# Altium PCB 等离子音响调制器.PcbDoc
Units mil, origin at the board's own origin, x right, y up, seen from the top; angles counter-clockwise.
Board outline 3937.01 x 2362.2 mil, 2 copper layers (Top Layer, Bottom Layer); 73 components, 35 nets, 187 pads, 240 vias.
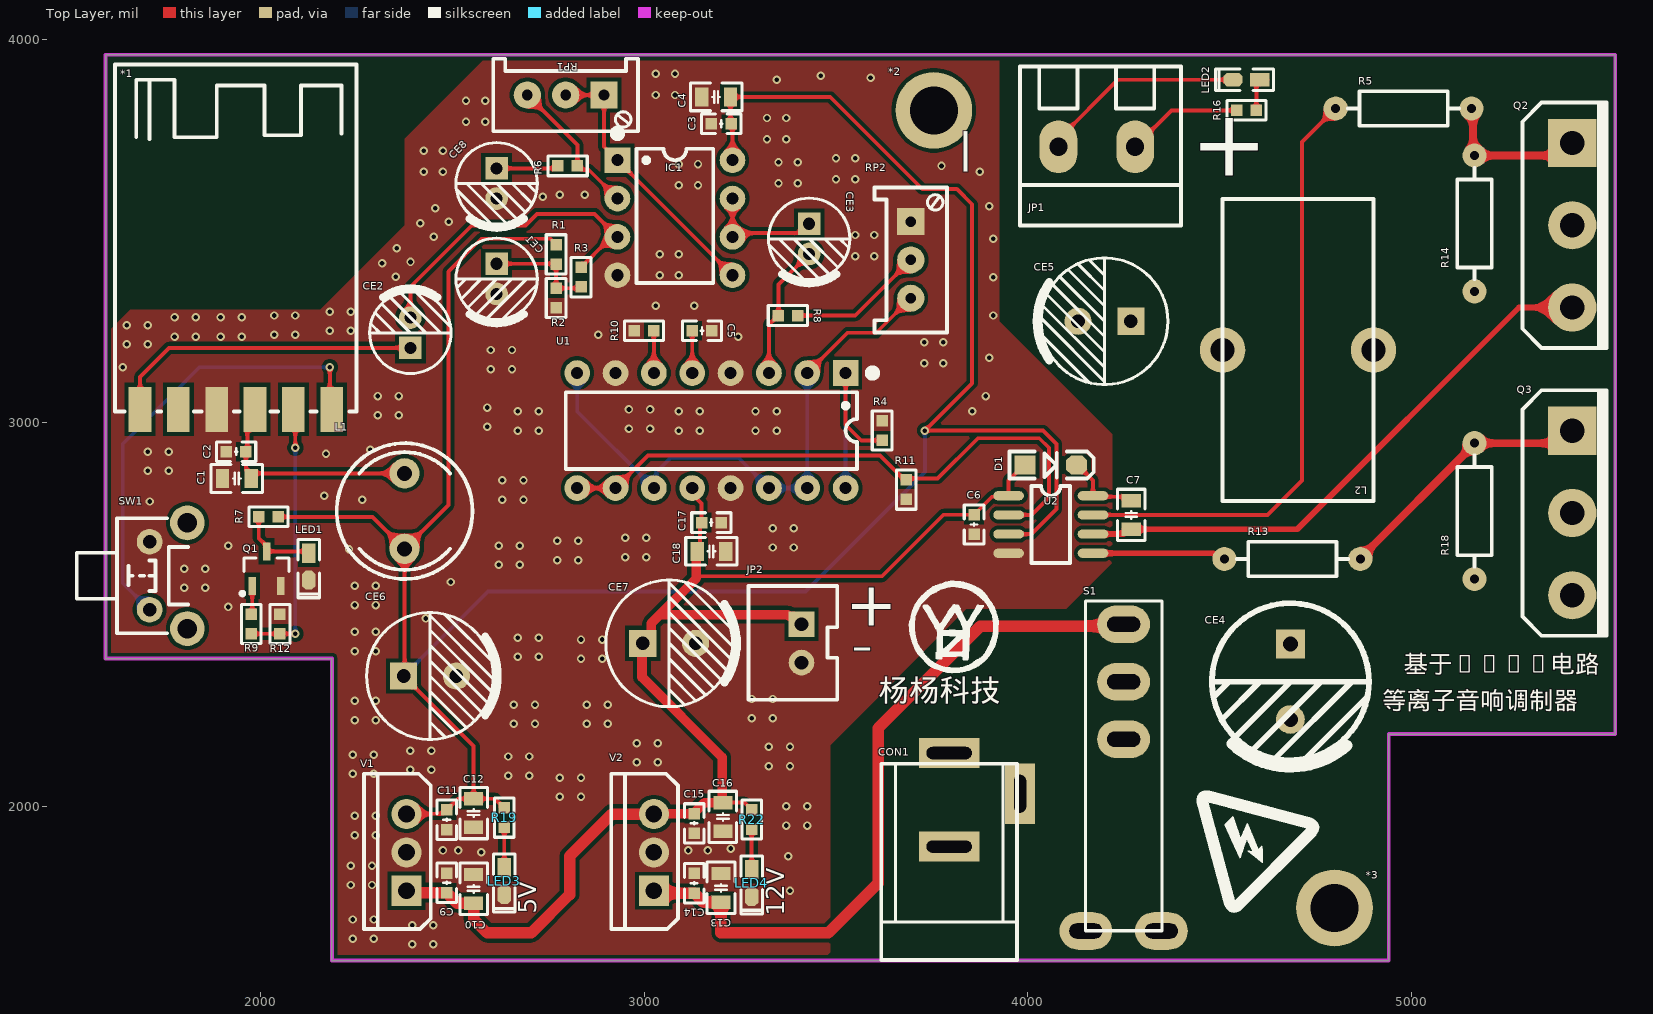
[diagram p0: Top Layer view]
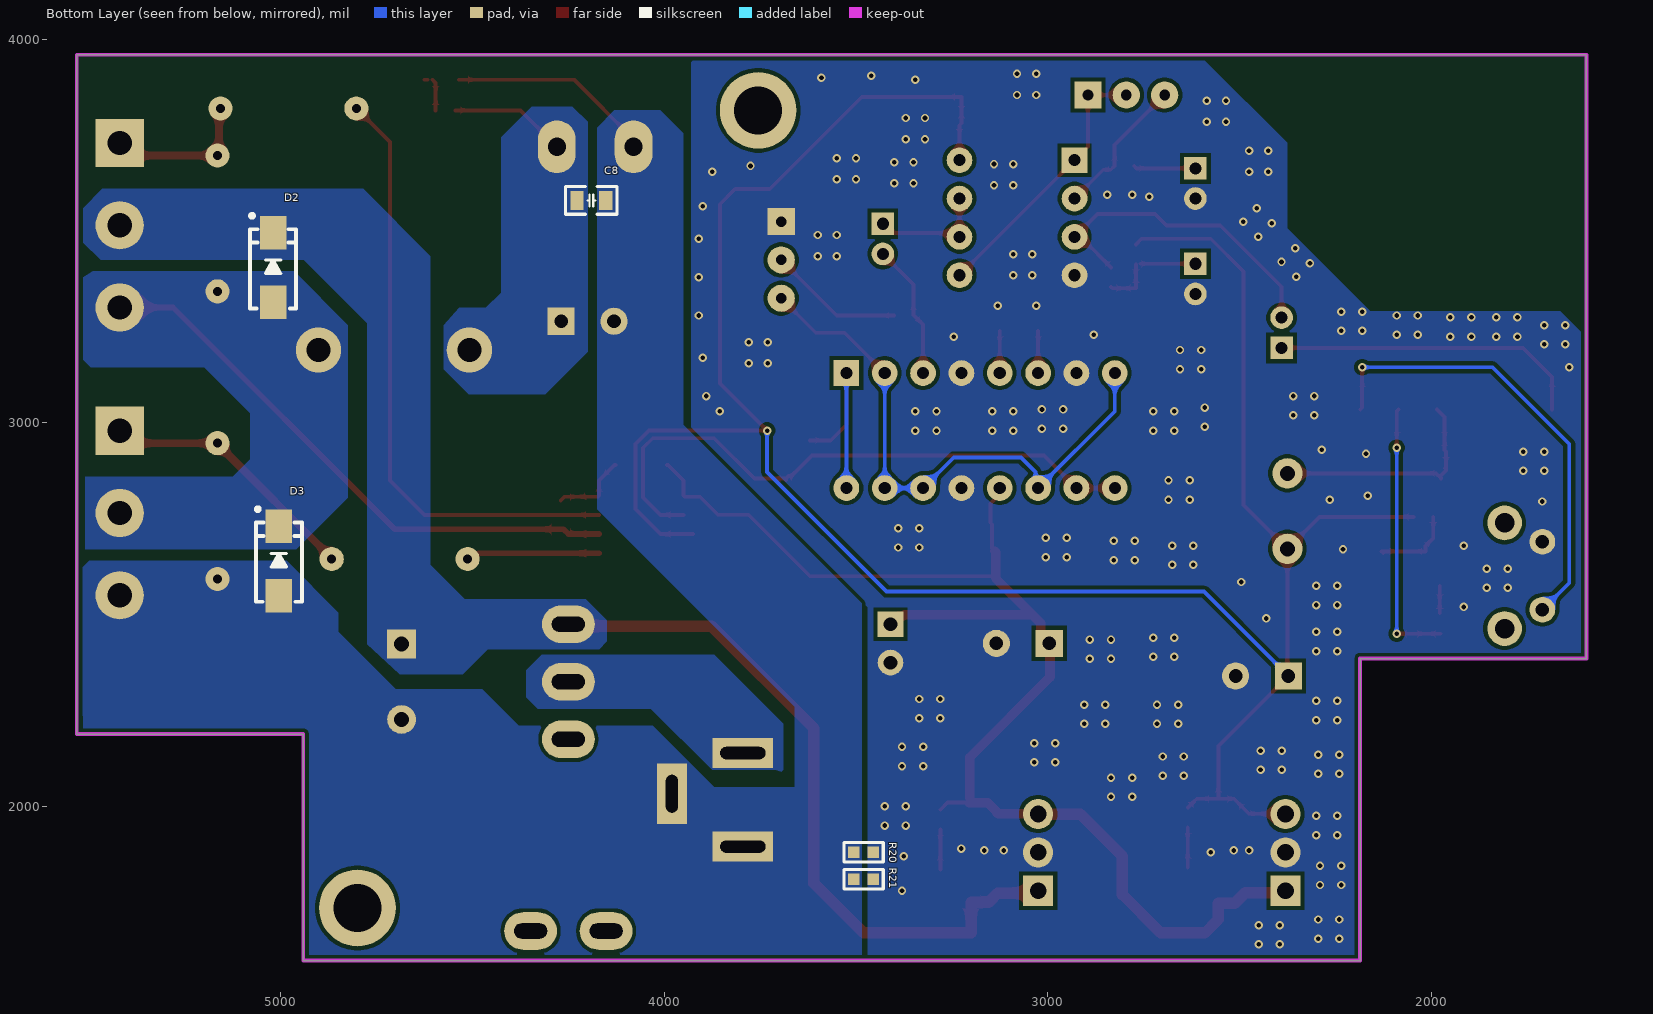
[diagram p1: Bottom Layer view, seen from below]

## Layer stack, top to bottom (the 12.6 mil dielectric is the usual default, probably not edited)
Top Solder: solder mask 0.4, Solder Resist, Dk 3.5
Top Layer: signal copper 1.4
Dielectric 1: dielectric 12.6, FR-4, Dk 4.8
Bottom Layer: signal copper 1.4
Bottom Solder: solder mask 0.4, Solder Resist, Dk 3.5

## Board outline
1595,2385.2 2185.55,2385.2 2185.55,1597.8 4941.46,1597.8 4941.46,2188.35 5532.01,2188.35 5532.01,3960 1595,3960

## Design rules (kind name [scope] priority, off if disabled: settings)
Clearance [All] p1: gap=10 ignorepadtopadclearanceinfootprint=FALSE except(0: Arc-Hole Track-Hole SMDPad-Hole THPad-Hole Via-Hole Fill-Hole Poly-Hole Region-Hole Text-Hole)
PlaneConnect [All] p1: planeconnectstyle=Direct reliefexpansion=20 reliefentries=4 reliefconductorwidth=10 reliefairgap=10
PolygonConnect [All] p1: connectstyle=Direct reliefconductorwidth=10 reliefentries=4 polygonreliefangle="90 Angle" airgapwidth=10
RoutingVias [All] p1: holewidth=28 width=50 viastyle="Through Hole" minholewidth=28 minwidth=50 maxholewidth=28 maxwidth=50
SolderMaskExpansion [All] p1: expansion=4 istentingtop=FALSE
Width [All] p1: maxlimit=10 minlimit=10 preferedwidth=10
29 further rules are at their usual default settings.

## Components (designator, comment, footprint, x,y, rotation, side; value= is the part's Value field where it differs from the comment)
*1 "MH-M18蓝牙音频模块" MH-M18蓝牙音频模块 1620,3935 r270 top
*2 "M3" "M3 125X200" 3755,3815 r0 top
*3 "M3" "M3 125X200" 4800,1735 r0 top
C1 "105" "C 0805_L" 1937.4,2855 r0 top
C2 "104" "C 0603_L" 1935.59,2925 r0 top
C3 "104" "C 0603_L" 3200.59,3780 r0 top
C4 "105" "C 0805_L" 3187.4,3850 r0 top
C5 "1nF" "C 0603_L" 3150.59,3240 r0 top
C6 "104" "C 0603_L" 3860,2735 r90 top
C7 "105\1uF" "C 0805_L" 4270,2760 r90 top
C8 "104" "C 0805_L" 4190,3580 r180 bottom
C9 "104" "C 0603_L" 2485,1800.59 r270 top
C10 "105" "C 0805_L" 2555,1785 r270 top
C11 "104" "C 0603_L" 2485,1965 r90 top
C12 "105" "C 0805_L" 2555,1982.4 r90 top
C13 "105" "C 0805_L" 3200,1787.6 r270 top
C14 "104" "C 0603_L" 3130,1799.41 r270 top
C15 "104" "C 0603_L" 3130,1955.59 r90 top
C16 "105" "C 0805_L" 3205,1972.4 r90 top
C17 "104" "C 0603_L" 3175,2740 r180 top
C18 "105" "C 0805_L" 3175,2665 r180 top
CE1 "22uF/16V" "CAP 2.0*5*11" 2615,3375.63 r270 top
CE2 "22uF/16V" "CAP 2.0*5*11" 2390,3235 r90 top
CE3 "10uF/16V" "CAP 2.0*5*11" 3430,3480 r270 top
CE4 "47uF/35V" "CAP 5.0*10*12.5" 4685,2325 r270 top
CE5 "47uF/35V" "CAP 3.5*8*11.5" 4200,3265 r180 top
CE6 "10uF/16V" "CAP 3.5*8*11.5 - GD" 2441.1,2340 r0 top
CE7 "10uF/16V" "CAP 3.5*8*11.5 - GD" 3065,2425 r0 top
CE8 "22uF/16V" "CAP 2.0*5*11" 2615,3624.37 r270 top
CON1 "3.5*1.3" DC-005 3795,1895 r270 top
D1 "FR107" SOD-123 4060,2890 r0 top
D2 "SS210" SMA 5020,3405 r90 bottom
D3 "SS210" SMA 5005,2640 r90 bottom
IC1 "NE5532" DIP8-300 3080,3535 r0 top
JP1 "HDR-1X2" KF128-5.08-2P 4180,3720 r180 top
JP2 "HDR-1X2" XH2.54-LI-2P 3410,2425 r270 top
L1 "10uH" PK0810 2375,2770 r270 top
L2 "33uH" 65125 4705,3190 r180 top
LED1 "蓝色" "LED 0603Y" 2125,2625 r270 top
LED2 "红色" "LED 0603Y" 4570,3895 r180 top
LED3 "红色" "LED 0603Y" 2635,1805 r270 top
LED4 "红色" "LED 0603Y" 3280,1800 r270 top
Q1 "SS8050" SOT23-3N 2015,2620 r0 top
Q2 "IRFP250" TO247A 5420,3515.43 r270 top
Q3 "IRFP250" TO247A 5420,2765 r270 top
R1 "22K" "R 0603_L" 2770,3439.41 r90 top
R2 "22K" "R 0603_L" 2770,3325.59 r90 top
R3 "22K" "R 0603_L" 2835,3380 r270 top
R4 "1K" "R 0603_L" 3620,2980 r270 top
R5 "10" "RS 1/4W" 4980,3820 r180 top
R6 "5K" "R 0603_L" 2800,3670 r180 top
R7 "1K" "R 0603_L" 2020,2755 r180 top
R8 "10K" "R 0603_L" 3374.41,3280 r0 top
R9 "1K" "R 0603_L" 1975,2475.59 r270 top
R10 "5K" "R 0603_L" 2999.41,3240 r0 top
R11 "10K" "R 0603_L" 3682.77,2825.89 r270 top
R12 "10K" "R 0603_L" 2050,2475.59 r270 top
R13 "10" "RS 1/4W" 4690,2645 r180 top
R14 "10K" "RS 1/4W" 5165,3520 r90 top
R16 "1K" "R 0603_L" 4570.59,3815 r180 top
R18 "10K" "RS 1/4W" 5165,2770 r90 top
R19 "1K" "R 0603_L" 2635,1970.59 r90 top
R20 "0" "R 0603_L" 3480,1880 r180 bottom
R21 "0" "R 0603_L" 3480,1810 r180 bottom
R22 "1K" "R 0603_L" 3280,1965.59 r90 top
RP1 "250K" 3296W 2795,3855 r180 top
RP2 "10K" 3296W 3695,3425 r270 top
S1 "钮子开关" MS-102-C4 4250,2320.67 r90 top
SW1 "6x6x5" "TSW DIP-6*6*6_V" 1710,2601.42 r270 top
U1 "TL494" DIP16-300_MH 3175,2980 r270 top
U2 "EG2104" SOP8 3951,2811 r0 top
V1 "78xx" TO220A 2380,1880 r90 top
V2 "78xx" TO220A 3025,1880 r90 top

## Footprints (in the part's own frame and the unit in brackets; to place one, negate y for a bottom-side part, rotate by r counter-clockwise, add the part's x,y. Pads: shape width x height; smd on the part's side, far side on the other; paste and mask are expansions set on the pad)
3296W [mm] "Precise Multi-Winding Adjustable Resistor"
  rect 1.8x1.8 hole 0.7: 1(-2.54,0)
  round 1.8 hole 0.7: 2(0,0) 3(2.54,0)
  silkscreen extent -4.8,-2.4 4.8,2.4, body extent -4.75,-2.4 4.75,2.4, height 11.52
65125 [mm] "直插电感"
  round 3 hole 1.6: 1(-5,0) 2(5,0)
  silkscreen extent -5,-10 5,10
"C 0603_L" [mil] "无极性贴片电容                                       淘宝ID:黄晶宝石"
  rect 30x30 smd: 1(-25.59,0) 2(25.59,0)
  silkscreen extent -51,-26 51,26, body extent -31,-16 31,16, height 32
"C 0805_L" [mil] "无极性贴片电容                                        淘宝ID:黄晶宝石"
  rect 35x50 smd: 1(-37.4,0) 2(37.4,0)
  silkscreen extent -67,-36 67,36, body extent -39,-24 39,24, height 20
"CAP 2.0*5*11" [mm] "脚距2mm直径5mm高度11mm                 淘宝ID:黄晶宝石"
  rect 1.5x1.5 hole 0.8: 1(-1,0)
  round 1.5 hole 0.8: 2(1,0)
  silkscreen extent -2.7,-2.7 2.96,2.7, body extent -2.5,-2.5 2.51,2.5, height 11.04
"CAP 3.5*8*11.5" [mm] "脚距3.5mm直径8mm高度11.5mm"
  rect 1.8x1.8 hole 0.9: 1(-1.75,0)
  round 1.8 hole 0.9: 2(1.75,0)
  silkscreen extent -4.2,-4.2 4.5,4.2, body extent -4,-4 4.01,4, height 11.53
"CAP 3.5*8*11.5 - GD" [mm] "脚距3.5mm直径8mm高度11.5mm"
  rect 1.8x1.8 hole 0.9: 1(-1.75,0)
  round 1.8 hole 0.9: 2(1.75,0)
  silkscreen extent -4.2,-4.2 4.5,4.2, body extent -4,-4 4.01,4, height 11.54
"CAP 5.0*10*12.5" [mm] "脚距5mm直径10mm高度12.5mm"
  rect 1.9x1.9 hole 1: 1(-2.5,0)
  round 1.9 hole 1: 2(2.5,0)
  silkscreen extent -5.2,-5.21 5.64,5.2, body extent -5,-5.01 5.01,4.99, height 12.55
DC-005 [mm] "5.5*2.1mm，DC30V,2.5A      淘宝ID:黄晶宝石"
  rect 2x4 hole 0.8 slot 3 at 90 deg: 1(-6.2,0) 2(0,0)
  rect 4x2 hole 0.8 slot 2.5 at 0 deg: 3(-3.5,4.7)
  silkscreen extent -5.48,-4.5 7.5,4.5, body extent -6.55,-4.5 7.5,4.8, height 11.2
DIP8-300 [mm] "9.4*7.6*3.8(长宽高）"
  rect 1.7x1.7 hole 0.8: 1(-3.81,3.81)
  round 1.7 hole 0.8: 2(-3.81,1.27) 3(-3.81,-1.27) 4(-3.81,-3.81) 5(3.81,-3.81) 6(3.81,-1.27) 7(3.81,1.27) 8(3.81,3.81)
  silkscreen extent -4.06,-4.32 2.54,5.84, body extent -3.93,-4.7 3.93,4.7, height 4.5
DIP16-300_MH [mm] "带底座 19.3*7.6*3.8(长宽高）"
  rect 1.7x1.7 hole 0.8: 1(-3.81,8.89)
  round 1.7 hole 0.8: 2(-3.81,6.35) 3(-3.81,3.81) 4(-3.81,1.27) 5(-3.81,-1.27) 6(-3.81,-3.81) 7(-3.81,-6.35) 8(-3.81,-8.89) 9(3.81,-8.89) 10(3.81,-6.35) 11(3.81,-3.81) 12(3.81,-1.27) 13(3.81,1.27) 14(3.81,3.81) 15(3.81,6.35) 16(3.81,8.89)
  silkscreen extent -4.06,-9.65 2.54,10.92, body extent -4.98,-10.25 5,10.25, height 7.5
KF128-5.08-2P [mm] "螺钉式接线端子，脚距5.08mm"
  oval 2.5x3.5 hole 1.2: 1(-2.54,0) 2(2.54,0)
  silkscreen extent -5.59,-5.31 5.08,5.21, body extent -5.58,-5.3 5.08,5.2, height 14.15
"LED 0603Y" [mil] "黄色0603LED                              淘宝ID:黄晶宝石"
  rect 50x35 smd: 1(-35,0)
  oct 50x35 smd: 2(35,0)
  silkscreen extent -71,-28 81,28, body extent -32,-16 31,16, height 18
"M3 125X200" [mil] "M3螺丝孔，孔125Mil，焊盘200Mil"
  round 200 hole 125: 1(0,0)
MH-M18蓝牙音频模块 [mm]
  rect 3x1.5 smd: 1(22.86,14.351) 2(22.86,11.811) 3(22.86,9.271) 4(22.86,6.731) 5(22.86,4.191) 6(22.86,1.651)
  silkscreen extent 0,0 23,16
MS-102-C4 [mm] "弯脚钮子开关"
  oval 2.5x3.5 hole 1 slot 2.2 at 90 deg unplated: 0(-16.4,-2.5) 0(-16.4,2.5) 1(-3.7,0) 2(0.11,0) 3(3.92,0)
  silkscreen extent -16.38,-2.54 5.46,2.54
PK0810 [mm] "5*9*12mm(脚距，直径，高）"
  round 2 hole 1: 1(-2.5,0) 2(2.5,0)
  silkscreen extent -4.5,-4.5 4.5,4.5, body extent -4.5,-4.5 4.5,4.5, height 12.02
"R 0603_L" [mil] "1/10W贴片电阻                 淘宝ID:黄晶宝石"
  rect 30x30 smd: 1(-25.59,0) 2(25.59,0)
  silkscreen extent -51,-26 51,26, body extent -31,-16 31,16, height 16
"RS 1/4W" [mm] "直插色环电阻，脚距9mm，直径2.3mm  淘宝ID:黄晶宝石"
  round 1.6 hole 0.6: 1(-4.5,0) 2(4.5,0)
  silkscreen extent -3.68,-1.14 3.68,1.14, body extent -4.72,-1.16 4.73,1.16, height 2.32
SMA [mm] "4.5x2.6*2.2mm（长宽高，不包括引脚）"
  rect 2.2x1.75 smd: 1(-2.3,0) 2(2.3,0)
  silkscreen extent -2.7,-1.52 3.56,1.52, body extent -2.52,-1.3 2.57,1.3, height 2.15
SOD-123 [mil] "2.7x1.6X1.1mm（长宽高，不包括引脚） 淘宝ID:黄晶宝石"
  rect 55x50 smd: 1(-67.5,0)
  oct 55x50 smd: 2(67.5,0)
  silkscreen extent -108,-35 112,35, body extent -73,-31 73,31, height 48
SOP8 [mil] "封装库来自淘宝卖家 ID：黄晶宝石"
  oval 80x24 smd: 1(-1,-1) 2(-1,-51) 3(-1,-101) 4(-1,-151) 5(219,-151) 6(219,-101) 7(219,-51) 8(219,-1)
  silkscreen extent 59,-176 159,24, body extent -4,-174 234,24, height 63
SOT23-3N [mm] "3x1.3x1mm(长宽高)    封装库来自淘宝卖家 ID：黄晶宝石"
  rect 0.5x1.2 smd: 1(-0.95,-1.143) 2(0.95,-1.143) 3(0,1.143)
  silkscreen extent -1.72,-1.78 1.5,0.7, body extent -1.5,-1.2 1.5,1.2, height 1.05
TO220A [mm] "220，3脚晶体管  封装库来自淘宝卖家 ID：黄晶宝石"
  rect 2x2 hole 1.1: 1(-2.54,0)
  round 2 hole 1.1: 2(0,0) 3(2.54,0)
  silkscreen extent -5.08,-1.6 5.21,2.82, body extent -5.15,-1.53 5.15,2.9, height 18.5
TO247A [mm] "247，3脚立式封装  封装库来自淘宝卖家 ID：黄晶宝石"
  rect 3.2x3.2 hole 1.6: 1(-5.45,0)
  round 3.2 hole 1.6: 2(0,0) 3(5.45,0)
  silkscreen extent -8.13,-3.3 8.13,2.29, body extent -7.75,-3 7.75,2, height 24
"TSW DIP-6*6*6_V" [mm] "侧按轻触开关 6*6*6mm"
  round 2.3 hole 1.3: 0(-3.5,2.5) 0(3.5,2.5)
  round 1.7 hole 0.9: 1(-2.25,0) 2(2.25,0)
  silkscreen extent -3.81,-4.83 3.81,2.54, body extent -4.18,-4.72 4.18,4.13, height 7.47
XH2.54-LI-2P [mm] "接插件，2P  淘宝ID:黄晶宝石   店铺网址:https://shop463601444.taobao.com"
  rect 1.7x1.7 hole 0.9: 1(-1.27,0)
  round 1.7 hole 0.9: 2(1.27,0)
  silkscreen extent -3.81,-3.51 3.74,2.37, body extent -3.77,-3.3 3.77,2.4, height 7.05

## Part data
*2 *3: "铜柱孔"
C1 C2 C3 C4 C5 C6 C7 C8 C9 C10 C11 C12 C13 C14 C15 C16 C17 C18: library part C, "贴片电容"
CE1 CE2 CE3 CE4 CE5 CE6 CE7 CE8: library part CE, "直插电解电容"
CON1: library part P-DC, "低压电源接口"
D1: "快恢复整流二极管"
D2 D3: "肖特基二极管"
IC1: "双路低噪声音频运放"
JP1 JP2: library part "Header 2", "2P接插件"
L1: library part L-PK, "工字电感"
L2: library part L-MR, "功率磁环电感"
LED1 LED2 LED3 LED4: library part LED-SMD, "贴片LED"
Q1: library part 8050-SMD, "高频放大-NPN型"
Q2 Q3: "功率型N沟场效应管"
R1 R2 R3 R4 R6 R7 R8 R9 R10 R11 R12 R16 R19 R20 R21 R22: library part R, "贴片电阻"
R5 R13 R14 R18: library part R-S, "色环电阻"
RP1 RP2: library part RP, "单联电位器"
S1: library part MTS-102
SW1: library part "TSW DIP-6x6_V", "侧按直插6x6轻触开关"
U1: "开关电源控制芯片"
U2: "半桥驱动芯片"
V1 V2: "LM78XX系列线性稳压芯片"

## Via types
v1: diameter 22, hole 12, Top Layer to Bottom Layer, tented both sides, 240 vias

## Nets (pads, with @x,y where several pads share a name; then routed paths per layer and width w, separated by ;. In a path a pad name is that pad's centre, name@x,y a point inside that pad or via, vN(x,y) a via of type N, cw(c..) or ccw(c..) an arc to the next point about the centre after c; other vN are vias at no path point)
+5: C3.2 C4.2 C11.2 C12.2 CE6.1 IC1.8 L1.2 R1.2 R7.1 R19.2 U2.3 V1.3 | length 6414.1
  Top Layer w10: R7.1 2291.57,2755 2373.43,2673.15 2373.43,2671.57 L1.2 ; V1.3 2380.59,1980.59 2475,1980.59 C11.2 2514.22,2019.8 C12.2 ; R19.2 2611.38,2019.8 C12.2 ; R1.2 2755,3480 2575,3480 2489.33,3394.33 2489.33,2785.9 L1.2 ; C4.2 3224.8,3781.38 C3.2 3230,3776.18 IC1.8 ; C4.2@3225,3850 3485,3850 3725,3610 3815,3610 3855,3570 3855,3103.14 v1(3731.86,2980) 4040,2980 4075,2945 4075,2775 4010,2710 U2.3 U2.3@3925,2710 ; L1.2 2375,2342.8 CE6.1 2555,2157.2 C12.2
  Bottom Layer w10: CE6.1 2592.2,2560 3420,2560 3731.86,2871.86 v1(3731.86,2980)
+5_Vref: RP2.3 U1.2 U1.8 U1.11 U1.14 U1.15 | length 1520.4
  Top Layer w10: U1.2 3530,3235 3605,3235 RP2.3
  Bottom Layer w10: U1.8 2825,3030 U1.11 3031.77,2836.77 3031.77,2871.77 3037.39,2877.39 3070,2910 3245,2910 U1.14 U1.15 U1.2
+12: C6.2 C9.2 C10.2 C15.2 C16.2 C17.2 C18.2 CE7.1 D1.1 JP2.1 R22.2 U1.12 U2.1 V1.1 V2.3 | length 3527.2
  Top Layer w10: U1.12 3125,2814.6 3149.41,2790.18 C17.2 3145,2735.59 3145,2672.4 C18.2 ; 3135.48,2600 3620,2600 3780.59,2760.59 C6.2 3906.74,2807.32 3947.32,2807.32 U2.1 3950,2850 3990,2890 D1.1 ; C16.2 3261.38,2009.8 R22.2
  Top Layer w25: V2.3 3026.18,1981.18 C15.2 3132.5,1983.68 3132.5,1985.36 3156.95,2009.8 C16.2 ; C18.2 3135.48,2662.88 3135.48,2600 3135.48,2594.52 3040.95,2500 ; C16.2@3202.88,2022.3 3202.88,2128.02 2993.98,2336.92 2993.98,2422.88 CE7.1 3017.98,2446.88 3017.98,2477.02 3040.95,2500 ; JP2.1 3389.04,2495.96 3378.43,2495.96 3374.39,2500 3040.95,2500
  Top Layer w30: V1.1 2385,1775 C9.2 2512.4,1747.6 C10.2 2555,1705 2590,1670 2705,1670 2805,1770 2805,1870 2915,1980 V2.3
AGND: *1.4 C1.1 C2.1 C3.1 C4.1 C5.2 C6.1 C9.1 C10.1 C11.1 C12.1 C13.1 C14.1 C15.1 C16.1 C17.1 C18.1 CE1.2 CE6.2 CE7.2 CE8.2 IC1.4 JP2.2 LED1.2 LED3.2 LED4.2 Q1.2 R2.1 R4.1 R10.1 R11.2 R12.1 R20.2 R21.2 RP2.1 SW1.1 U1.4 U1.7 U1.13 U2.4 V1.2 V2.2
  other v1: 2395,1640 2450,1640 2240,1655 2295,1655 2395,1690 2450,1690 2240,1705 2295,1705 3380,1780 2235,1795 2290,1795 2235,1845 2290,1845 3375,1870 2575,1880 2475,1885 2515,1885 3115,1885 3165,1885 3225,1890 2245,1925 2300,1925 3370,1950 3425,1950 2245,1975 2300,1975 3370,2000 3425,2000 2780,2025 2835,2025 2780,2075 2835,2075 2645,2080 2700,2080 2240,2085 2295,2085 2390,2095 2445,2095 3325,2105 3380,2105 2980,2115 3035,2115 2645,2130 2700,2130 2240,2135 2295,2135 2390,2145 2445,2145 3325,2155 3380,2155 2980,2165 3035,2165 2660,2215 2715,2215 2850,2215 2905,2215 2245,2225 2300,2225 3280,2230 3335,2230 2660,2265 2715,2265 2850,2265 2905,2265 2245,2275 2300,2275 3280,2280 3335,2280 2835,2385 2890,2385 2670,2390 2725,2390 2245,2405 2300,2405 2835,2435 2890,2435 2670,2440 2725,2440 2245,2455 2300,2455 2430,2490 1915,2520 2245,2525 2300,2525 1800,2570 1855,2570 2245,2575 2300,2575 2495,2585 1800,2620 1855,2620 2620,2630 2675,2630 2772.69,2642.15 2827.69,2642.15 2950,2650 3005,2650 2230,2670 3335,2675 3390,2675 1915,2680 2620,2680 2675,2680 2772.69,2692.15 2827.69,2692.15 2950,2700 3005,2700 3335,2725 3390,2725 1710,2795 2265,2800 2630,2800 2685,2800 2165,2810 2630,2850 2685,2850 1705,2875 1760,2875 2170,2920 1705,2925 1760,2925 2285,2930 2670,2980 2725,2980 3090,2980 3145,2980 3290,2980 3345,2980 2960,2985 3015,2985 2590,2990 2305,3020 2360,3020 2670,3030 2725,3030 3090,3030 3145,3030 3290,3030 3345,3030 3855,3030 2960,3035 3015,3035 2590,3040 2305,3070 2360,3070 3890,3070 2600,3140 2655,3140 1640,3145 3730,3155 3780,3155 3900,3170 2600,3190 2655,3190 1650,3205 1705,3205 3730,3210 3780,3210 1775,3225 1830,3225 1895,3225 1950,3225 3245,3225 2035,3230 2090,3230 2880,3230 2180,3240 2235,3240 1650,3255 1705,3255 1775,3275 1830,3275 1895,3275 1950,3275 2035,3280 2090,3280 3910,3280 2180,3290 2235,3290 3030,3305 3130,3305 3910,3380 2351.46,3380.75 3040,3385 3090,3385 2316.11,3416.11 2390.36,3419.64 3550,3435 3600,3435 3040,3440 3090,3440 2355,3455 3910,3480 2451.46,3485.75 3550,3490 3600,3490 2416.11,3521.11 2490.36,3524.64 2455,3560 3900,3565 2735,3590 2780,3595 2845,3595 3090,3620 3140,3620 3350,3625 3400,3625 3500,3635 3550,3635 2425,3655 2475,3655 3875,3655 3775,3670 3090,3675 3140,3675 3350,3680 3400,3680 3500,3690 3550,3690 2425,3710 2475,3710 3320,3740 3370,3740 2535,3785 2585,3785 3320,3795 3370,3795 2535,3840 2585,3840 3030,3855 3080,3855 3345,3895 3590,3900 3460,3905 3030,3910 3080,3910
MA1: C7.1 D2.1 D3.2 L2.1 Q2.3 Q3.2 R14.1 U2.6 | length 1494.7
  Top Layer w15: U2.6 4249.91,2710 4262.5,2722.6 C7.1 4702.6,2722.6 5280.87,3300.87 Q2.3
Net*1_1: *1.1 SW1.2 | length 1196.1
  Top Layer w10: v1(2180,3145) 2180,3040 *1.1
  Bottom Layer w10: SW1.2 1640,2582.83 1640,2945 1840,3145 v1(2180,3145)
Net*1_2: *1.2 R9.2 R12.2 | length 702.1
  Top Layer w10: R9.2 R12.2 v1(2090,2450) ; *1.2 2090,3030 v1(2090,2935)
  Bottom Layer w10: v1(2090,2450) v1(2090,2935)
Net*1_3: *1.3 C1.2 C2.2 L1.1 | length 594.3
  Top Layer w10: C1.2 1974.8,2855.93 1987.3,2868.43 L1.1 ; C1.2@1974.8,2862.5 1961.18,2876.12 C2.2 1965,2928.82 1965,3015 *1.3
Net*1_6: *1.6 CE2.1 | length 821.3
  Top Layer w10: *1.6 1685,3120 1760.63,3195.63 CE2.1
NetC5_1: C5.1 U1.5 | length 110
  Top Layer w10: U1.5 C5.1
NetC7_2: C7.2 D1.2 U2.8 | length 204.3
  Top Layer w10: D1.2 4130,2890 4170,2850 U2.8 4172.68,2807.32 4260.08,2807.32 C7.2
NetC8_1: C8.1 CE5.1 JP1.1 L2.2 R16.2 | length 304.4
  Top Layer w10: JP1.1 4375,3815 R16.2
NetCE1_1: CE1.1 R1.1 R2.2 R3.2 | length 272.8
  Top Layer w10: CE1.1 R1.1@2758.82,3415 ; R1.1 R2.2 2831.77,3351.18 R3.2
NetCE2_2: CE2.2 IC1.3 R3.1 | length 852.1
  Top Layer w10: CE2.2 2390,3355 2550,3515 2690,3515 2720,3545 2870,3545 IC1.3 2919.11,3474.11 2903.52,3474.11 R3.1
NetCE3_1: CE3.1 IC1.6 IC1.7 | length 314.2
  Top Layer w10: IC1.7 IC1.6 3239.84,3494.84 3405.47,3494.84 CE3.1
NetCE3_2: CE3.2 R8.1 U1.3 | length 354.1
  Top Layer w10: U1.3 3325,3256.18 R8.1 3350,3281.18 3350,3360.63 CE3.2
NetCE8_1: CE8.1 R6.2 | length 162
  Top Layer w10: CE8.1 2768.15,3663.74 R6.2
NetCON1_1: CON1.1 S1.2
NetIC1_1: IC1.1 IC1.5 RP1.1 RP1.2 | length 708.8
  Top Layer w10: RP1.2 RP1.1 2895,3720 IC1.1 IC1.5
NetIC1_2: IC1.2 R6.1 RP1.3 | length 378.7
  Top Layer w10: RP1.3 2825.59,3724.41 R6.1 2835.59,3660 2855,3660 IC1.2
NetLED1_1: LED1.1 Q1.3 R7.2 | length 220.6
  Top Layer w10: R7.2 1994.41,2699.37 2015,2678.78 Q1.3 2130,2665 LED1.1
NetLED2_1: LED2.1 R16.1 | length 91.2
  Top Layer w10: R16.1 4596.18,3886.18 LED2.1 ; LED2.1@4617.5,3895 LED2.1@4625,3895
NetLED3_1: LED3.1 R19.1 | length 105
  Top Layer w10: LED3.1 R19.1
NetLED4_1: LED4.1 R22.1 | length 105
  Top Layer w10: LED4.1 R22.1
NetQ1_1: Q1.1 R9.1 | length 71.2
  Top Layer w10: R9.1@1977.6,2503.78 Q1.1
NetQ2_1: Q2.1 R5.1 R14.2 | length 394.7
  Top Layer w20: R5.1 5161.08,3816.08 5161.08,3701.08 R14.2 5387.17,3697.17 Q2.1
NetQ3_1: Q3.1 R13.1 R18.2 | length 694
  Top Layer w20: R13.1 4867.17,2647.17 5165,2945 R18.2 5387.6,2947.17 Q3.1
NetR4_2: R4.2 U1.1 U1.16 | length 546.8
  Top Layer w10: U1.1 3525,2995 3565.59,2954.41 R4.2
  Bottom Layer w10: U1.16 U1.1
NetR5_2: R5.2 U2.7 | length 1588.7
  Top Layer w10: U2.7 4625,2760 4715,2850 4715,3732.17 R5.2
NetR8_2: R8.2 RP2.2 | length 355.1
  Top Layer w10: R8.2 3550,3280 RP2.2
NetR10_2: R10.2 U1.6 | length 110
  Top Layer w10: U1.6 R10.2
NetR13_2: R13.2 U2.5 | length 349
  Top Layer w15: U2.5 4483.49,2660 4498.49,2645 R13.2
PGND: C8.2 CE4.2 CE5.2 CON1.2 CON1.3 D3.1 JP1.2 LED2.2 Q3.3 R18.1 R20.1 R21.1 | length 539
  Top Layer w10: JP1.2 4080,3739.69 4235.31,3895 LED2.2
PWM: R11.1 U1.9 U1.10 U2.2 | length 1599.5
  Top Layer w10: U1.9 U1.10 3010,2915 3615,2915 3668.51,2861.49 3675.54,2861.49 3682.03,2855 3765,2855 3870,2960 4030,2960 4055,2935 4055,2805 4010,2760 U2.2 ; R11.1 R11.1@3684.15,2852.87
VCC: C13.2 C14.2 CE4.1 D2.2 Q2.2 S1.3 V2.1 | length 1880.7
  Top Layer w30: V2.1 3031.18,1773.82 C14.2 3153.62,1750.2 C13.2 3200,1685 3200,1670 3480,1670 3610,1800 3610,2204.14 3875.86,2470 S1.3@4245,2470
pads on no net: *1.5 *2.1 *3.1 S1.0 S1.1 SW1.0

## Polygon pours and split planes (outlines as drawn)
AGND on Bottom Layer "NONET_L-01_P-001" (solid, pour order 8): 1599,3225.82 1664,3290.82 2159,3290.82 2375.29,3507.12 2375.29,3730.08 2596.03,3950.82 3919,3950.82 3929,3940.82 3929,3260.82 3929,2978.79 3469,2518.79 3469,1595.82 2189,1595.82 2189,2385.82 1594,2385.82
PGND on Bottom Layer "NONET_L-01_P-001" (solid, pour order 6): 4010,3815 4130,3815 4175,3770 4175,2775 3660,2260 3660,1605 3655,1610 3485,1610 3485,2530 3950,2995 3950,3755
NetC8_1 on Bottom Layer "NONET_L-01_P-001" (solid, pour order 5): 4575,3255 4575,3140 4510,3075 4310,3075 4200,3185 4200,3785 4240,3825 4345,3825 4425,3745 4425,3340 4465,3300 4535,3300
VCC on Bottom Layer "NONET_L-01_P-001" (solid, pour order 1): 4205,2540 4150,2485 4150,2430 4170,2410 4460,2410 4525,2345 4690,2345 4775,2422.92 4775,3260 4940,3425 5470,3425 5515,3470 5515,3560 5465,3610 4785,3610 4610,3435 4610,2630 4520,2540
PGND on Bottom Layer "NONET_L-01_P-001" (solid, pour order 4): 4985,2640 5500,2640 5520,2620 5520,2240 5515,2235 5515,2195 4940,2195 4935,2200 4935,1610 3585,1610 3580,1605 3580,2040 3590,2050 3870,2050 4030,2210 4380,2210 4475,2305 4700,2305 4850,2455 4850,2505
MA1 on Bottom Layer "NONET_L-01_P-001" (solid, pour order 2): 5490,3395 4965,3395 4825,3255 4825,2805 4960,2670 5510,2670 5510,2860 5125,2860 5080,2905 5080,3025 5200,3145 5495,3145 5515,3165 5515,3380
NetCON1_1 on Bottom Layer "NONET_L-01_P-001" (solid, pour order 0): 3710,2095 3875,2095 4035,2255 4330,2255 4360,2285 4360,2355 4320,2395 3870,2395 3690,2215 3690,2095 3695,2090
AGND on Top Layer "NONET_L-01_P-001" (solid, pour order 7): 1595,3230 1660,3295 2155,3295 2375.43,3515.43 2375.43,3741 2589.42,3955 3915,3955 3925,3945 3925,3265 4220,2970 4220,2635 4100,2515 3840,2515 3485,2160 3485,1620 3465,1600 2185,1600 2185,2390 1590,2390

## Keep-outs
Keep-Out Layer:
  the board outline again, w10

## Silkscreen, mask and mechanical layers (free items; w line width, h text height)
Top Overlay:
  drawing of 2081 lines, arcs and shapes, not listed
  text "-" at 4031.28,3635 h500 r90
  text "+" at 4425,3587.23 h300
  text "+" at 3525,2431.49 h200
  text "基于BUCK电路" at 4980.07,2332.25 h80
  text "-" at 3540,2330.76 h200
  text "杨杨科技" at 3611.97,2254.23 h100
  text "等离子音响调制器" at 4925,2237.25 h80
  text "5V" at 2734.04,1720 h80 r90
  text "12V" at 3380,1715 h80 r90
Bottom Solder:
  lines w30: 3780,1900 3680,1900 3610,1970 3610,2360 3790,2540 4135,2885 4135,3685 4095,3725 ; 3800,2150 3975,2325 4230,2325 ; 3805,1890 4348.43,1890 4685,2226.57 4701.57,2226.57 5015,2540 5025.43,2550.43 5420,2550.43 ; 3815,1925 3850,1890 3970,1890 3970,2015 ; 4265,2480 4470,2480 4540,2410 4685,2410 4680,2415 4680,3315 4870,3505 5025,3505 5409.57,3505 5420,3515.43 ; 4268.9,3711.1 4250,3692.2 4250,3283.9 4343.9,3190 4508.15,3190 ; 5420,3300.87 4975.87,3300.87 4905,3230 4905,2840 4980,2765 5425,2765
